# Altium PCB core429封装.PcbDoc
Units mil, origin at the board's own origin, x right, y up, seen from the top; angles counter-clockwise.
Board outline 6000 x 4000 mil, 2 copper layers (Top Layer, Bottom Layer); 4 components, 0 nets, 191 pads, 0 vias.
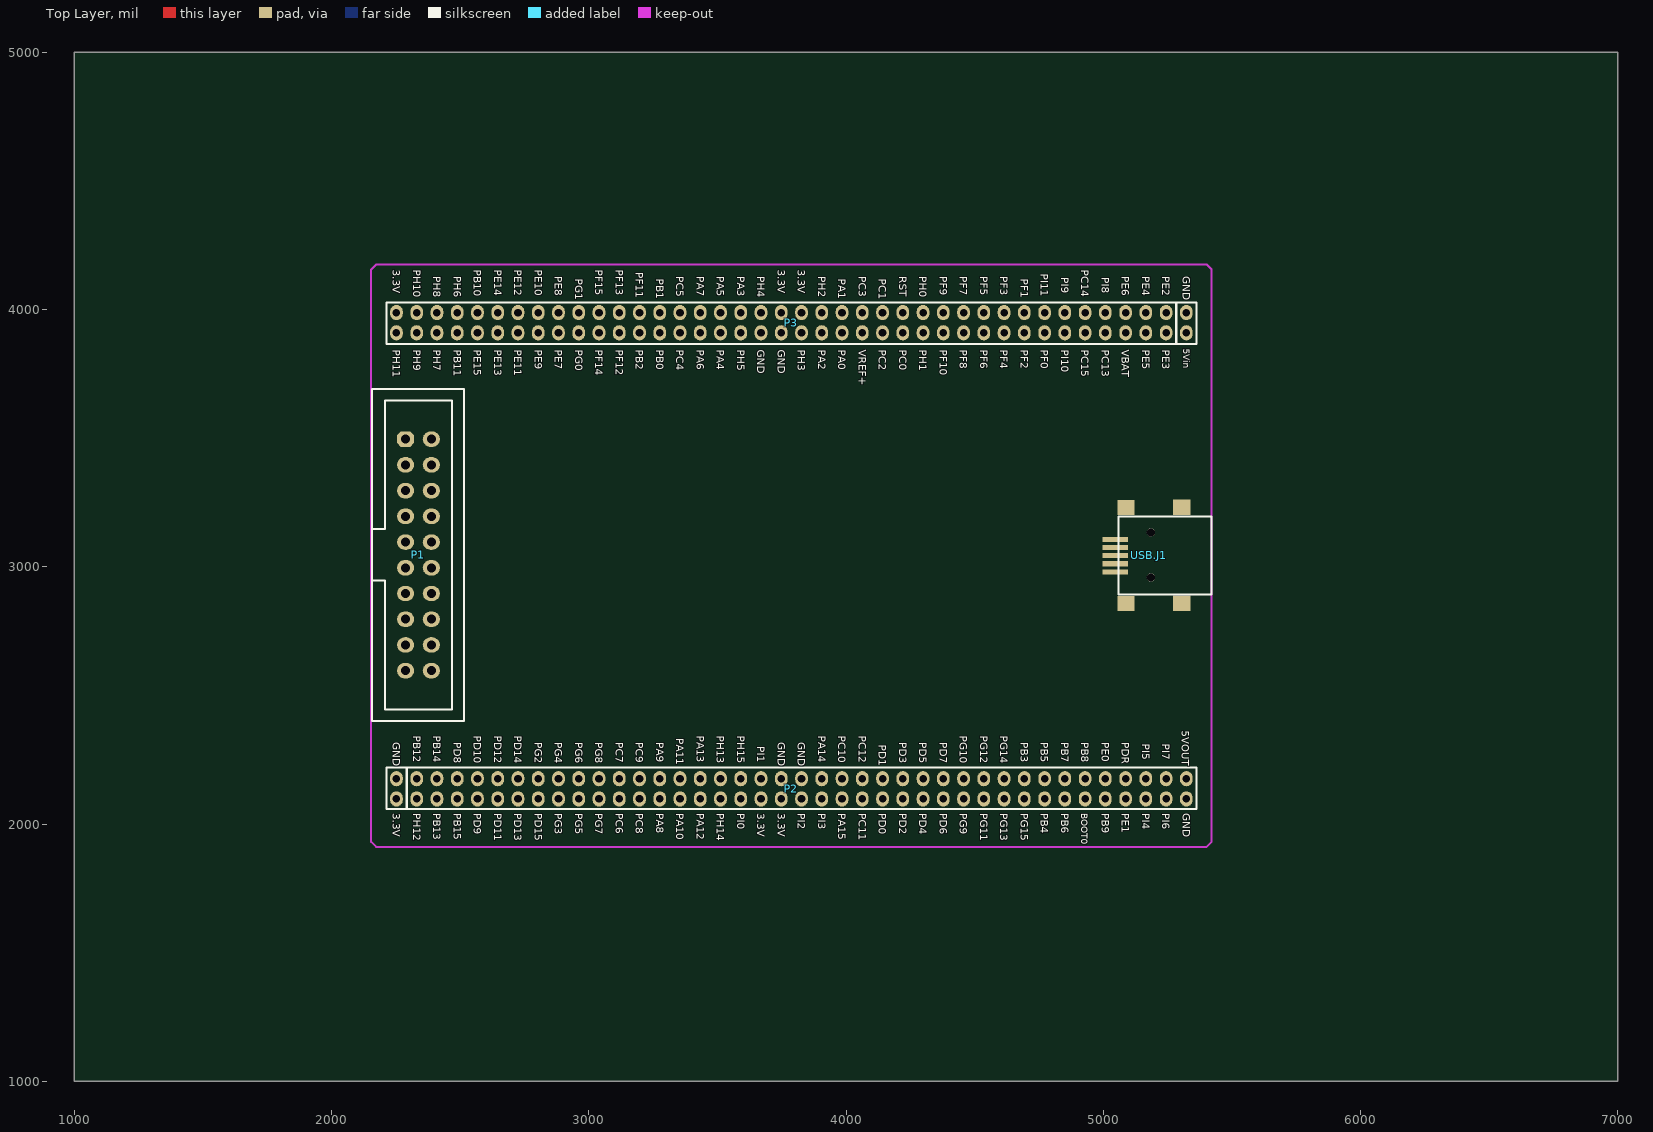
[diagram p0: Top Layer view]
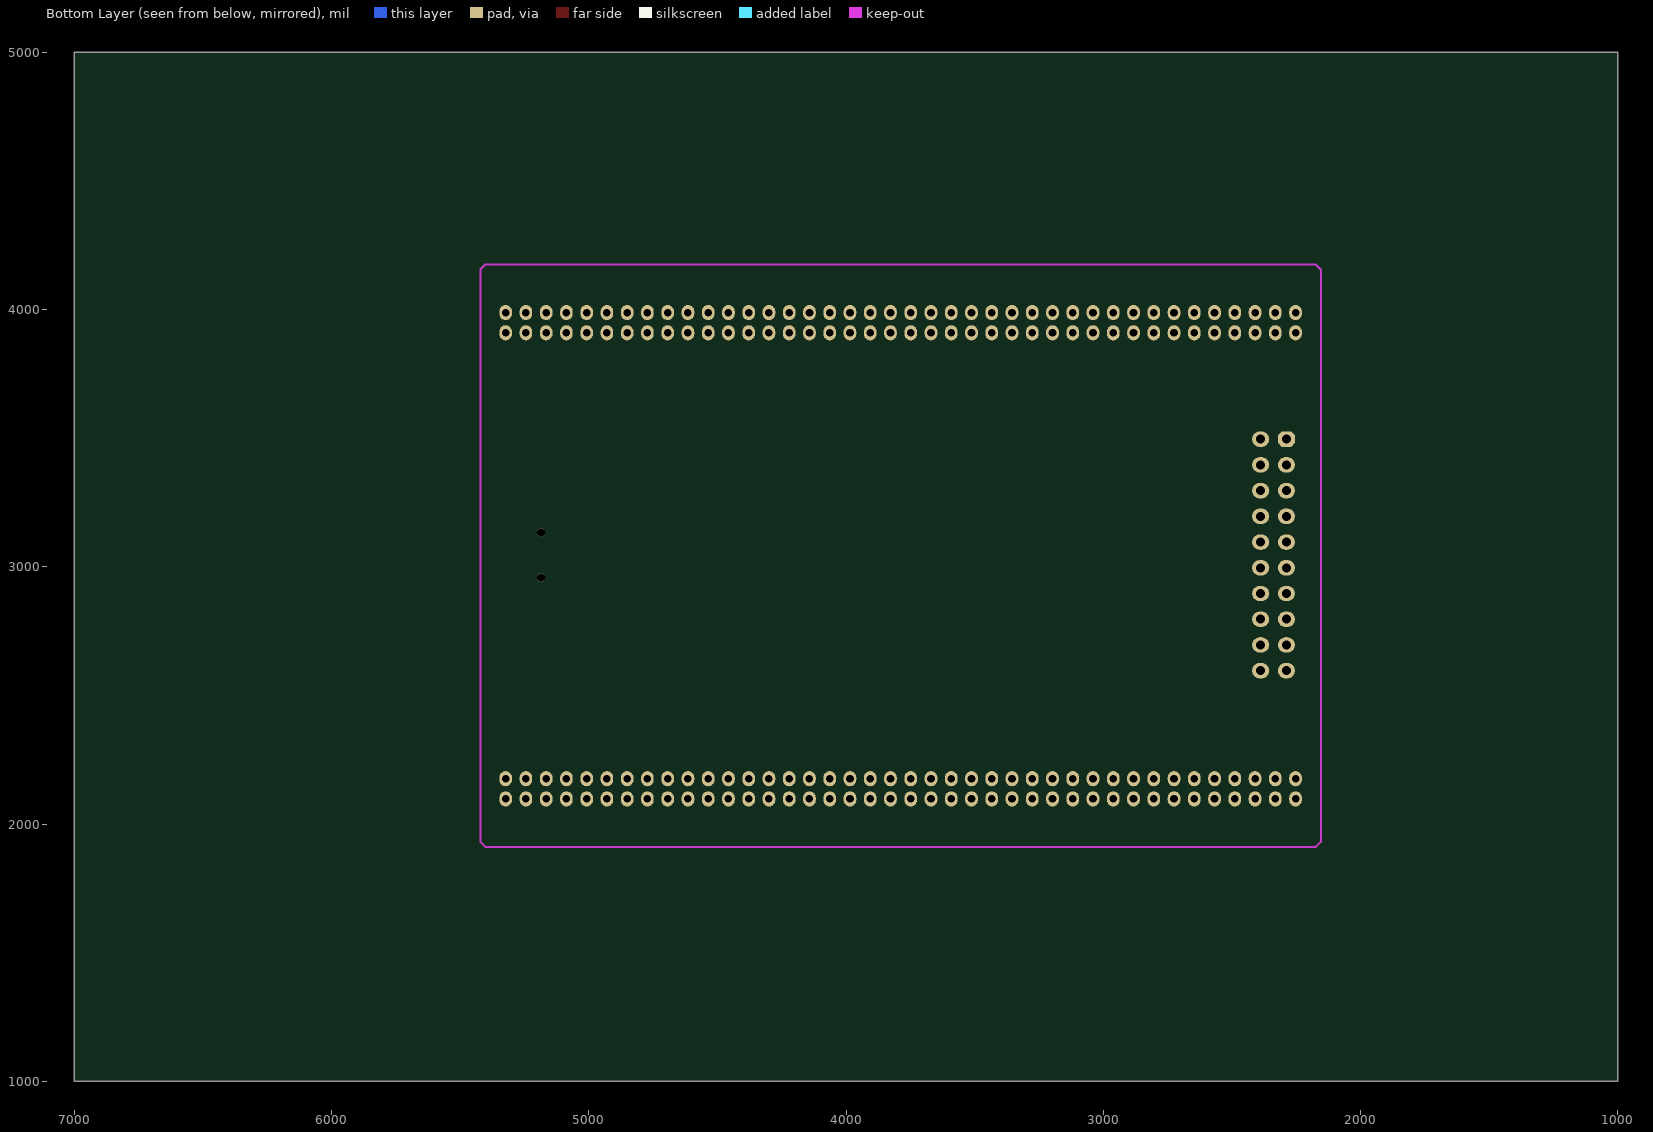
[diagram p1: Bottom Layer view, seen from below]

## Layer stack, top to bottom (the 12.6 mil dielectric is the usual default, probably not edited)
Top Solder: solder mask 0.4, Solder Resist, Dk 3.5
Top Layer: signal copper 1.4
Dielectric 1: dielectric 12.6, FR-4, Dk 4.8
Bottom Layer: signal copper 1.4
Bottom Solder: solder mask 0.4, Solder Resist, Dk 3.5

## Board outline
1000,1000 7000,1000 7000,5000 1000,5000

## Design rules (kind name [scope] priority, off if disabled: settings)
Clearance [All] p1: gap=10
PolygonConnect [All] p1: connectstyle=Relief reliefconductorwidth=10 reliefentries=4 polygonreliefangle="90 Angle" airgapwidth=10
RoutingVias [All] p1: holewidth=28 width=50 viastyle="Through Hole" minholewidth=28 minwidth=50 maxholewidth=28 maxwidth=50
SolderMaskExpansion [All] p1: expansion=4
Width [All] p1: maxlimit=10 minlimit=10 preferedwidth=10
30 further rules are at their usual default settings.

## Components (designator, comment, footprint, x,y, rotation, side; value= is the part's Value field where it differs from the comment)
P1 "20PIN_JTAG" 20PIN_JTAG 2288.05,3495.99 r0 top
P2 "Header 40X2" "Header 40X2 - 2mm" 2252.32,2097.48 r90 top
P3 "Header 40X2" "Header 40X2 - 2mm" 5323.18,3988.12 r270 top
USB.J1 "USB" USB2 5088.93,3228.28 r270 top

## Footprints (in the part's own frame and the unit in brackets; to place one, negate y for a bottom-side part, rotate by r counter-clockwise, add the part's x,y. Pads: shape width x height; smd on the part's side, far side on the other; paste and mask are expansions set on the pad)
20PIN_JTAG [mil]
  oct 67x60 hole 35: 1(0,0)
  oval 67x60 hole 35: 2(100,0) 3(0,-100) 4(100,-100) 5(0,-200) 6(100,-200) 7(0,-300) 8(100,-300) 9(0,-400) 10(100,-400) 11(0,-500) 12(100,-500) 13(0,-600) 14(100,-600) 15(0,-700) 16(100,-700) 17(0,-800) 18(100,-800) 19(0,-900) 20(100,-900)
  silkscreen extent -130,-1095 227,195
"Header 40X2 - 2mm" [mm]
  oval 1.5x1.25 hole 0.75: 1(0,0) 2(2,0) 3(0,-2) 4(2,-2) 5(0,-4) 6(2,-4) 7(0,-6) 8(2,-6) 9(0,-8) 10(2,-8) 11(0,-10) 12(2,-10) 13(0,-12) 14(2,-12) 15(0,-14) 16(2,-14) 17(0,-16) 18(2,-16) 19(0,-18) 20(2,-18) 21(0,-20) 22(2,-20) 23(0,-22) 24(2,-22) 25(0,-24) 26(2,-24) 27(0,-26) 28(2,-26) 29(0,-28) 30(2,-28) 31(0,-30) 32(2,-30) 33(0,-32) 34(2,-32) 35(0,-34) 36(2,-34) 37(0,-36) 38(2,-36) 39(0,-38) 40(2,-38) 41(0,-40) 42(2,-40) 43(0,-42) 44(2,-42) 45(0,-44) 46(2,-44) 47(0,-46) 48(2,-46) 49(0,-48) 50(2,-48) 51(0,-50) 52(2,-50) 53(0,-52) 54(2,-52) 55(0,-54) 56(2,-54) 57(0,-56) 58(2,-56) 59(0,-58) 60(2,-58) 61(0,-60) 62(2,-60) 63(0,-62) 64(2,-62) 65(0,-64) 66(2,-64) 67(0,-66) 68(2,-66) 69(0,-68) 70(2,-68) 71(0,-70) 72(2,-70) 73(0,-72) 74(2,-72) 75(0,-74) 76(2,-74) 77(0,-76) 78(2,-76) 79(0,-78) 80(2,-78)
  silkscreen extent -1,-78.99 3.1,1
USB2 [mm]
  round 0.8 hole 0.8: 0(2.413,2.435) 0(6.858,2.435)
  rect 0.5x2.5 smd: 1(6.299,-1.059) 2(5.499,-1.059) 3(4.699,-1.059) 4(3.899,-1.059) 5(3.099,-1.059)
  rect 1.5x1.7 smd: 6(-0.078,5.486) 7(9.4,5.486) 8(-0.053,0) 9(9.425,0)
  silkscreen extent 0.84,-0.76 8.54,8.44, body extent -0.66,-2.31 10.03,8.44, height 4

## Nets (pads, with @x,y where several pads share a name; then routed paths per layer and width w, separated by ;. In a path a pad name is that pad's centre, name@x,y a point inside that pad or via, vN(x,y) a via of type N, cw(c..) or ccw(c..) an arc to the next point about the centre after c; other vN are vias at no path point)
pads on no net: P1.1 P1.2 P1.3 P1.4 P1.5 P1.6 P1.7 P1.8 P1.9 P1.10 P1.11 P1.12 P1.13 P1.14 P1.15 P1.16 P1.17 P1.18 P1.19 P1.20 P2.1 P2.2 P2.3 P2.4 P2.5 P2.6 P2.7 P2.8 P2.9 P2.10 P2.11 P2.12 P2.13 P2.14 P2.15 P2.16 P2.17 P2.18 P2.19 P2.20 P2.21 P2.22 P2.23 P2.24 P2.25 P2.26 P2.27 P2.28 P2.29 P2.30 P2.31 P2.32 P2.33 P2.34 P2.35 P2.36 P2.37 P2.38 P2.39 P2.40 P2.41 P2.42 P2.43 P2.44 P2.45 P2.46 P2.47 P2.48 P2.49 P2.50 P2.51 P2.52 P2.53 P2.54 P2.55 P2.56 P2.57 P2.58 P2.59 P2.60 P2.61 P2.62 P2.63 P2.64 P2.65 P2.66 P2.67 P2.68 P2.69 P2.70 P2.71 P2.72 P2.73 P2.74 P2.75 P2.76 P2.77 P2.78 P2.79 P2.80 P3.1 P3.2 P3.3 P3.4 P3.5 P3.6 P3.7 P3.8 P3.9 P3.10 P3.11 P3.12 P3.13 P3.14 P3.15 P3.16 P3.17 P3.18 P3.19 P3.20 P3.21 P3.22 P3.23 P3.24 P3.25 P3.26 P3.27 P3.28 P3.29 P3.30 P3.31 P3.32 P3.33 P3.34 P3.35 P3.36 P3.37 P3.38 P3.39 P3.40 P3.41 P3.42 P3.43 P3.44 P3.45 P3.46 P3.47 P3.48 P3.49 P3.50 P3.51 P3.52 P3.53 P3.54 P3.55 P3.56 P3.57 P3.58 P3.59 P3.60 P3.61 P3.62 P3.63 P3.64 P3.65 P3.66 P3.67 P3.68 P3.69 P3.70 P3.71 P3.72 P3.73 P3.74 P3.75 P3.76 P3.77 P3.78 P3.79 P3.80 USB.J1.0 USB.J1.1 USB.J1.2 USB.J1.3 USB.J1.4 USB.J1.5 USB.J1.6 USB.J1.7 USB.J1.8 USB.J1.9

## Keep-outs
Keep-Out Layer:
  lines w8: 2153.89,1931.03 2153.89,4155.44 2173.57,4175.13 5401.92,4175.13 5421.61,4155.44 5421.61,1931.03 5401.92,1911.35 2173.57,1911.35 2153.89,1931.03

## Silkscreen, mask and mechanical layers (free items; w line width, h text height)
Top Overlay:
  text "3.3V" at 2238.22,4154.7 h30 r270
  text "PH10" at 2316.96,4154.7 h30 r270
  text "PB10" at 2553.18,4154.7 h30 r270
  text "PE14" at 2631.92,4154.7 h30 r270
  text "PE12" at 2710.66,4154.7 h30 r270
  text "PE10" at 2789.4,4154.7 h30 r270
  text "PF15" at 3025.62,4154.7 h30 r270
  text "PF13" at 3104.36,4154.7 h30 r270
  text "3.3V" at 3734.28,4154.7 h30 r270
  text "3.3V" at 3813.02,4154.7 h30 r270
  text "PC14" at 4915.37,4154.7 h30 r270
  text "PF11" at 3183.1,4144.7 h30 r270
  text "PI11" at 4757.89,4139.71 h30 r270
  text "PH8" at 2395.7,4129.71 h30 r270
  text "PH6" at 2474.44,4129.71 h30 r270
  text "PE8" at 2868.14,4129.71 h30 r270
  text "PC5" at 3340.58,4129.71 h30 r270
  text "PA7" at 3419.32,4129.71 h30 r270
  text "PA5" at 3498.06,4129.71 h30 r270
  text "PA3" at 3576.8,4129.71 h30 r270
  text "PH4" at 3655.54,4129.71 h30 r270
  text "PH2" at 3891.76,4129.71 h30 r270
  text "PC3" at 4049.24,4129.71 h30 r270
  text "RST" at 4206.72,4129.71 h30 r270
  text "PH0" at 4285.46,4129.71 h30 r270
  text "PF9" at 4364.2,4129.71 h30 r270
  text "PF7" at 4442.94,4129.71 h30 r270
  text "PF5" at 4521.67,4129.71 h30 r270
  text "PF3" at 4600.41,4129.71 h30 r270
  text "PE6" at 5072.85,4129.71 h30 r270
  text "PE4" at 5151.59,4129.71 h30 r270
  text "PE2" at 5230.33,4129.71 h30 r270
  text "GND" at 5309.07,4129.71 h30 r270
  text "PI9" at 4836.63,4124.71 h30 r270
  text "PI8" at 4994.11,4124.71 h30 r270
  text "PG1" at 2946.88,4119.71 h30 r270
  text "PB1" at 3261.84,4119.71 h30 r270
  text "PA1" at 3970.5,4119.71 h30 r270
  text "PC1" at 4127.98,4119.71 h30 r270
  text "PF1" at 4679.15,4119.71 h30 r270
  text "5Vin" at 5311.04,3848.44 h25 r270
  text "PH11" at 2238.22,3842.74 h30 r270
  text "PH9" at 2316.96,3842.74 h30 r270
  text "PH7" at 2395.7,3842.74 h30 r270
  text "PB11" at 2474.44,3842.74 h30 r270
  text "PE15" at 2553.18,3842.74 h30 r270
  text "PE13" at 2631.92,3842.74 h30 r270
  text "PE11" at 2710.66,3842.74 h30 r270
  text "PE9" at 2789.4,3842.74 h30 r270
  text "PE7" at 2868.14,3842.74 h30 r270
  text "PG0" at 2946.88,3842.74 h30 r270
  text "PF14" at 3025.62,3842.74 h30 r270
  text "PF12" at 3104.36,3842.74 h30 r270
  text "PB2" at 3183.1,3842.74 h30 r270
  text "PB0" at 3261.84,3842.74 h30 r270
  text "PC4" at 3340.58,3842.74 h30 r270
  text "PA6" at 3419.32,3842.74 h30 r270
  text "PA4" at 3498.06,3842.74 h30 r270
  text "PH5" at 3576.8,3842.74 h30 r270
  text "GND" at 3655.54,3842.74 h30 r270
  text "GND" at 3734.28,3842.74 h30 r270
  text "PH3" at 3813.02,3842.74 h30 r270
  text "PA2" at 3891.76,3842.74 h30 r270
  text "PA0" at 3970.5,3842.74 h30 r270
  text "VREF+" at 4049.24,3842.74 h30 r270
  text "PC2" at 4127.98,3842.74 h30 r270
  text "PC0" at 4206.72,3842.74 h30 r270
  text "PH1" at 4285.46,3842.74 h30 r270
  text "PF10" at 4364.2,3842.74 h30 r270
  text "PF8" at 4442.94,3842.74 h30 r270
  text "PF6" at 4521.67,3842.74 h30 r270
  text "PF4" at 4600.41,3842.74 h30 r270
  text "PF2" at 4679.15,3842.74 h30 r270
  text "PF0" at 4757.89,3842.74 h30 r270
  text "PI10" at 4836.63,3842.74 h30 r270
  text "PC15" at 4915.37,3842.74 h30 r270
  text "PC13" at 4994.11,3842.74 h30 r270
  text "VBAT" at 5072.85,3842.74 h30 r270
  text "PE5" at 5151.59,3842.74 h30 r270
  text "PE3" at 5230.33,3842.74 h30 r270
  text "5VOUT" at 5305.46,2362.13 h28 r270
  text "PB12" at 2316.96,2342.4 h30 r270
  text "PB14" at 2395.7,2342.4 h30 r270
  text "PD10" at 2553.18,2342.4 h30 r270
  text "PD12" at 2631.92,2342.4 h30 r270
  text "PD14" at 2710.66,2342.4 h30 r270
  text "PA13" at 3419.32,2342.4 h30 r270
  text "PH13" at 3498.06,2342.4 h30 r270
  text "PH15" at 3576.8,2342.4 h30 r270
  text "PA14" at 3891.76,2342.4 h30 r270
  text "PC10" at 3970.5,2342.4 h30 r270
  text "PC12" at 4049.24,2342.4 h30 r270
  text "PG10" at 4442.94,2342.4 h30 r270
  text "PG12" at 4521.67,2342.4 h30 r270
  text "PG14" at 4600.41,2342.4 h30 r270
  text "PA11" at 3340.58,2332.4 h30 r270
  text "GND" at 2238.22,2317.41 h30 r270
  text "PD8" at 2474.44,2317.41 h30 r270
  text "PG2" at 2789.4,2317.41 h30 r270
  text "PG4" at 2868.14,2317.41 h30 r270
  text "PG6" at 2946.88,2317.41 h30 r270
  text "PG8" at 3025.62,2317.41 h30 r270
  text "PC7" at 3104.36,2317.41 h30 r270
  text "PC9" at 3183.1,2317.41 h30 r270
  text "PA9" at 3261.84,2317.41 h30 r270
  text "GND" at 3734.28,2317.41 h30 r270
  text "GND" at 3813.02,2317.41 h30 r270
  text "PD3" at 4206.72,2317.41 h30 r270
  text "PD5" at 4285.46,2317.41 h30 r270
  text "PD7" at 4364.2,2317.41 h30 r270
  text "PB3" at 4679.15,2317.41 h30 r270
  text "PB5" at 4757.89,2317.41 h30 r270
  text "PB7" at 4836.63,2317.41 h30 r270
  text "PB8" at 4915.37,2317.41 h30 r270
  text "PE0" at 4994.11,2317.41 h30 r270
  text "PDR" at 5072.85,2317.41 h30 r270
  text "PI5" at 5151.59,2312.41 h30 r270
  text "PI7" at 5230.33,2312.41 h30 r270
  text "PD1" at 4127.98,2307.41 h30 r270
  text "PI1" at 3655.54,2302.41 h30 r270
  text "BOOT0" at 4914.31,2042.12 h25.59 r270
  text "3.3V" at 2238.22,2041.06 h30 r270
  text "PH12" at 2316.96,2041.06 h30 r270
  text "PB13" at 2395.7,2041.06 h30 r270
  text "PB15" at 2474.44,2041.06 h30 r270
  text "PD9" at 2553.18,2041.06 h30 r270
  text "PD11" at 2631.92,2041.06 h30 r270
  text "PD13" at 2710.66,2041.06 h30 r270
  text "PD15" at 2789.4,2041.06 h30 r270
  text "PG3" at 2868.14,2041.06 h30 r270
  text "PG5" at 2946.88,2041.06 h30 r270
  text "PG7" at 3025.62,2041.06 h30 r270
  text "PC6" at 3104.36,2041.06 h30 r270
  text "PC8" at 3183.1,2041.06 h30 r270
  text "PA8" at 3261.84,2041.06 h30 r270
  text "PA10" at 3340.58,2041.06 h30 r270
  text "PA12" at 3419.32,2041.06 h30 r270
  text "PH14" at 3498.06,2041.06 h30 r270
  text "PI0" at 3576.8,2041.06 h30 r270
  text "3.3V" at 3655.54,2041.06 h30 r270
  text "3.3V" at 3734.28,2041.06 h30 r270
  text "PI2" at 3813.02,2041.06 h30 r270
  text "PI3" at 3891.76,2041.06 h30 r270
  text "PA15" at 3970.5,2041.06 h30 r270
  text "PC11" at 4049.24,2041.06 h30 r270
  text "PD0" at 4127.98,2041.06 h30 r270
  text "PD2" at 4206.72,2041.06 h30 r270
  text "PD4" at 4285.46,2041.06 h30 r270
  text "PD6" at 4364.2,2041.06 h30 r270
  text "PG9" at 4442.94,2041.06 h30 r270
  text "PG11" at 4521.67,2041.06 h30 r270
  text "PG13" at 4600.41,2041.06 h30 r270
  text "PG15" at 4679.15,2041.06 h30 r270
  text "PB4" at 4757.89,2041.06 h30 r270
  text "PB6" at 4836.63,2041.06 h30 r270
  text "PB9" at 4994.11,2041.06 h30 r270
  text "PE1" at 5072.85,2041.06 h30 r270
  text "PI4" at 5151.59,2041.06 h30 r270
  text "PI6" at 5230.33,2041.06 h30 r270
  text "GND" at 5309.07,2041.06 h30 r270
